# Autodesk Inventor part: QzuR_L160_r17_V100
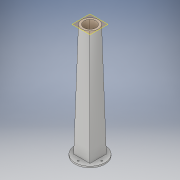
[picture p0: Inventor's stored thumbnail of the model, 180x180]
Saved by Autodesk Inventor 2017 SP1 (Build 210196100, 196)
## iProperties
Part Number: QzuR_L160_r17_V100
Material: Generisch
Document SubType Name: Modeling
Designer: haesner
Density: 1 g/cm^3
Appearance: Vorgabe
Part Number: QzuR_L160_r17_V100_3D-Druck
Author: haesner
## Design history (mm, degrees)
sketch "Skizze1"
  geometry: L1 (-11.5, 11.5)-(11.5, 11.5); L2 (11.5, 11.5)-(11.5, -11.5); L3 (11.5, -11.5)-(-11.5, -11.5); L4 (-11.5, -11.5)-(-11.5, 11.5); L5 (0, -16.1)-(0, 16.1) reference; L6 (-16.1, 0)-(16.1, 0) reference; 1 further point
  constraints: 8 end point, 2 parallel, 2 perpendicular, 1 horizontal, 2 other
  dimensions: "d1" = 23 distance of L1.start L1.end (computed from d0)
workplane "Arbeitsebene1"
sketch "Skizze2"
  geometry: C1 r 11.5 at (0, 0); 1 further point
  constraints: 1 centre point, 1 coincident
  dimensions: "d3" = 23 diameter of C1
feature "Erhebung1" sketch "Skizze2" dims "d4" = 0, "d5" = 90 deg, "d6" = 0, "d7" = 90 deg
feature "Wandung1" dims "d8" = 3
sketch "Skizze3"
  geometry: L1 (0, 0)-(0, -23) reference; L2 (23, 0)-(0, 0) reference; L3 (23, -23)-(23, 0) reference; L4 (0, -23)-(23, -23) reference; C1 r 21 at (11.5, -11.5); 1 further point
  constraints: 1 centre point, 1 coincident
  dimensions: "d9" = 42 diameter of C1
extrude "Extrusion1" join sketch "Skizze3" distance "d10" = 2; taper "d11" = 0 deg
sketch "Skizze4"
  geometry: L1 (0, -16.5)-(16.5, 0); L2 (16.5, 0)-(0, 16.5); L3 (0, 16.5)-(-16.5, 0); L4 (-16.5, 0)-(0, -16.5); L5 (29.4, 0)-(-29.4, 0) reference; L6 (0, -29.4)-(0, 29.4) reference; 1 further point
  constraints: 8 end point, 3 point on line, 2 parallel, 2 perpendicular
  dimensions: "d12" = 16.5 distance from line of L5 L1.start
hole "Bohrung1" sketch "Skizze4" at (0, -16.5), (-16.5, 0), (0, 16.5), (16.5, 0) diameter "d13" = 2.3; stored, may be unused: countersink angle "d17" = 90 deg, drill point angle "d19" = 118 deg; dims "d14" = 6, "d15" = 4, "d16" = 2, "d18" = 8
node "Volumenkörper1"
other parameters: "d0" = 17
